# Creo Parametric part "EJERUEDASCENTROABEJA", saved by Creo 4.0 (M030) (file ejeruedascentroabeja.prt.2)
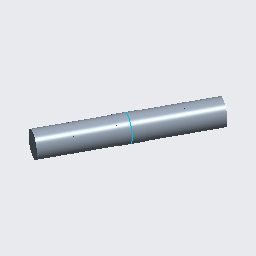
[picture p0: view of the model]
Units: millimeter Newton Second (mmNs); MM, TONNE, SECS

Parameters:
  MODELED_BY = "AJ"

Created from: MMNS_PART_SOLID.PRT

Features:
  1. datum plane "RIGHT"
  2. datum plane "TOP"
  3. datum plane "FRONT"
  4. coordinate system
  5. extrusion "Extrude 1"
  6. datum plane "DTM1"
  7. extrusion "Extrude 2"
  8. datum plane "DTM2"
  9. sketch "Sketch 1"
  10. sketch "Sketch 1 (2)"
  11. extrusion "Extrude 3"
  12. mirror "Mirror 1"
  13. extrusion "Extrude 3 (2)"

Surfaces: 8 plane, 4 cylinder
